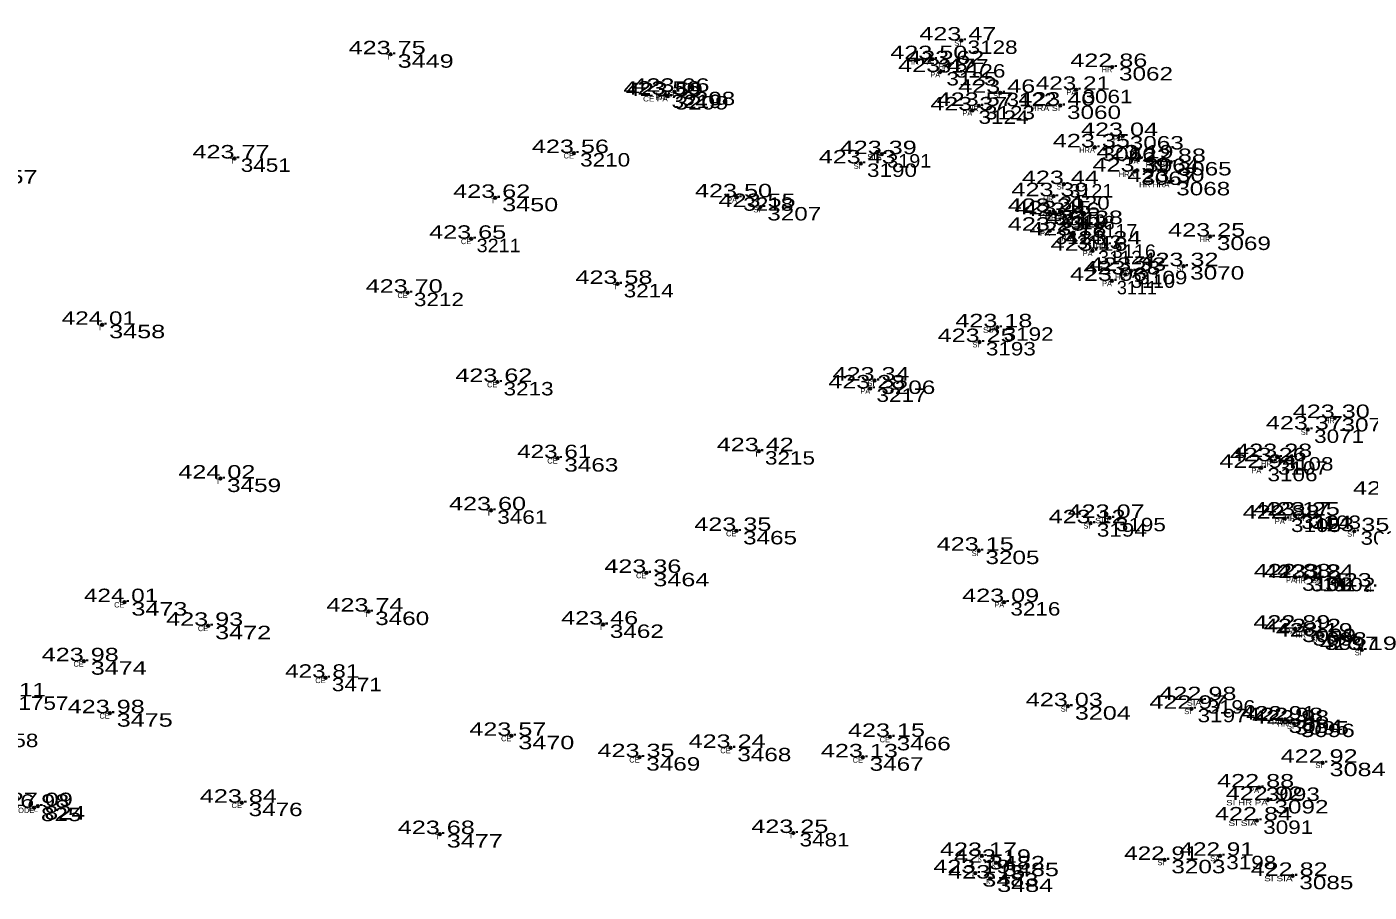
# Model space of a CAD drawing. Extents: x -639390 to -639074, y -1138747 to -1138358.
# Drawn here: x -639201.6 to -639126.7, y -1138617 to -1138568.7 of the extents above; entities that cross this region are included whole.
import ezdxf
from ezdxf.enums import TextEntityAlignment as Align

# ---------------------------------------------------------------- set-up
doc = ezdxf.new("R2010")
doc.units = 0
doc.header["$LTSCALE"] = 0.3
doc.header["$PDMODE"] = 32
doc.header["$PDSIZE"] = 0.15
for name, color, linetype in [('11', 7, 'Continuous'), ('12', 7, 'Continuous'), ('13', 7, 'Continuous'), ('57', 7, 'Continuous')]:
    doc.layers.add(name, color=color, linetype=linetype)

msp = doc.modelspace()

# ---------------------------------------------------------------- linework, layer by layer
at = {"layer": '11'}
for p in [(-639149.45, -1138569.5), (-639181.28, -1138570.27), (-639151.07, -1138570.54), (-639150.13, -1138570.82), (-639141.03, -1138570.98), (-639150.63, -1138571.26), (-639165.96, -1138572.52), (-639165.82, -1138572.6), (-639165.45, -1138572.36), (-639147.28, -1138572.42), (-639143.04, -1138572.25), (-639148.84, -1138573.4), (-639148.48, -1138573.15), (-639143.93, -1138573.13), (-639140.43, -1138574.83), (-639142, -1138575.46), (-639189.99, -1138576.08), (-639171.06, -1138575.78), (-639155.06, -1138576.36), (-639153.89, -1138575.84), (-639139.57, -1138576.08), (-639137.76, -1138576.28), (-639139.79, -1138576.81), (-639143.73, -1138577.51), (-639137.84, -1138577.39), (-639175.45, -1138578.28), (-639161.96, -1138578.25), (-639144.31, -1138578.19), (-639160.65, -1138578.79), (-639144.52, -1138579.06), (-639144.15, -1138579.2), (-639143.66, -1138579.29), (-639144.51, -1138580.11), (-639142.39, -1138579.74), (-639176.79, -1138580.56), (-639143.31, -1138580.37), (-639141.36, -1138580.88), (-639135.57, -1138580.44), (-639142.13, -1138581.23), (-639139.98, -1138582.35), (-639137.06, -1138582.09), (-639168.63, -1138583.08), (-639141.05, -1138582.91), (-639140.29, -1138582.55), (-639180.33, -1138583.57), (-639197.37, -1138585.36), (-639147.44, -1138585.5), (-639148.43, -1138586.32), (-639175.33, -1138588.55), (-639154.53, -1138588.91), (-639154.29, -1138588.47), (-639128.62, -1138590.56), (-639130.12, -1138591.2), (-639171.97, -1138592.8), (-639160.75, -1138592.41), (-639131.83, -1138592.74), (-639132.72, -1138593.34), (-639132.14, -1138592.97), (-639190.78, -1138593.94), (-639175.68, -1138595.71), (-639142.24, -1138596.43), (-639141.18, -1138596.13), (-639131.41, -1138596.17), (-639130.83, -1138596), (-639130.29, -1138596), (-639162, -1138596.86), (-639127.53, -1138596.88), (-639148.48, -1138597.96), (-639167.02, -1138599.2), (-639130.79, -1138599.45), (-639130.23, -1138599.48), (-639129.5, -1138599.47), (-639196.13, -1138600.83), (-639147.06, -1138600.83), (-639182.52, -1138601.36), (-639191.46, -1138602.15), (-639169.43, -1138602.08), (-639130.82, -1138602.31), (-639130.23, -1138602.51), (-639129.57, -1138602.75), (-639127.11, -1138603.5), (-639198.4, -1138604.13), (-639184.91, -1138605.05), (-639136.06, -1138606.3), (-639196.95, -1138607.03), (-639143.51, -1138606.64), (-639136.62, -1138606.78), (-639131.57, -1138607.38), (-639131.22, -1138607.47), (-639130.89, -1138607.61), (-639174.55, -1138608.29), (-639153.43, -1138608.35), (-639162.32, -1138608.96), (-639167.4, -1138609.48), (-639154.94, -1138609.49), (-639129.3, -1138609.79), (-639132.84, -1138611.17), (-639201.16, -1138612.3), (-639200.96, -1138612.21), (-639189.58, -1138612.02), (-639132.36, -1138611.87), (-639132.96, -1138613.01), (-639178.54, -1138613.77), (-639158.82, -1138613.71), (-639148.3, -1138614.99), (-639138.11, -1138615.21), (-639135.02, -1138614.98), (-639148.67, -1138615.95), (-639147.52, -1138615.37), (-639147.84, -1138616.25), (-639130.97, -1138616.1)]:
    msp.add_point(p, dxfattribs=at)

# ---------------------------------------------------------------- texts
at = {"layer": '12'}
for s, width, p in [('423.47 ', 1.4, (-639149.45, -1138569.5)), ('423.75 ', 1.4, (-639181.28, -1138570.27)), ('423.50 ', 1.4, (-639151.07, -1138570.54)), ('423.62 ', 1.4, (-639150.13, -1138570.82)), ('422.86 ', 1.4, (-639141.029, -1138570.98)), ('423.47 ', 1.4, (-639150.63, -1138571.26)), ('423.56 ', 1.4, (-639165.959, -1138572.52)), ('423.66 ', 1.4, (-639165.449, -1138572.36)), ('423.46 ', 1.4, (-639147.279, -1138572.42)), ('423.21 ', 1.35, (-639143.039, -1138572.25)), ('423.59 ', 1.4, (-639165.82, -1138572.6)), ('423.57 ', 1.4, (-639148.48, -1138573.15)), ('423.40 ', 1.4, (-639143.93, -1138573.13)), ('423.37 ', 1.4, (-639148.84, -1138573.4)), ('423.04 ', 1.4, (-639140.43, -1138574.83)), ('423.35 ', 1.4, (-639142, -1138575.46)), ('423.77 ', 1.4, (-639189.99, -1138576.08)), ('423.56 ', 1.4, (-639171.059, -1138575.78)), ('423.39 ', 1.4, (-639153.89, -1138575.84)), ('423.19 ', 1.4, (-639139.57, -1138576.08)), ('422.88 ', 1.4, (-639137.76, -1138576.28)), ('423.43 ', 1.4, (-639155.06, -1138576.36)), ('423.39 ', 1.4, (-639139.79, -1138576.81)), ('423.44 ', 1.4, (-639143.73, -1138577.51)), ('423.30 ', 1.4, (-639137.84, -1138577.39)), ('423.62 ', 1.4, (-639175.45, -1138578.28)), ('423.50 ', 1.4, (-639161.96, -1138578.25)), ('423.39 ', 1.4, (-639144.31, -1138578.19)), ('423.55 ', 1.4, (-639160.65, -1138578.79)), ('423.29 ', 1.4, (-639144.52, -1138579.06)), ('423.45 ', 1.4, (-639144.15, -1138579.2)), ('423.46 ', 1.4, (-639143.659, -1138579.29)), ('423.38 ', 1.4, (-639142.39, -1138579.74)), ('423.65 ', 1.4, (-639176.79, -1138580.56)), ('423.23 ', 1.4, (-639144.51, -1138580.11)), ('423.18 ', 1.4, (-639143.31, -1138580.37)), ('423.25 ', 1.4, (-639135.57, -1138580.44)), ('423.16 ', 1.4, (-639142.129, -1138581.23)), ('423.34 ', 1.4, (-639141.36, -1138580.88)), ('423.32 ', 1.4, (-639137.06, -1138582.09)), ('423.06 ', 1.4, (-639141.049, -1138582.91)), ('423.28 ', 1.4, (-639140.29, -1138582.55)), ('423.33 ', 1.4, (-639139.98, -1138582.35)), ('423.70 ', 1.4, (-639180.33, -1138583.57)), ('423.58 ', 1.4, (-639168.63, -1138583.08)), ('424.01 ', 1.35, (-639197.369, -1138585.36)), ('423.18 ', 1.4, (-639147.44, -1138585.5)), ('423.25 ', 1.4, (-639148.43, -1138586.32)), ('423.62 ', 1.4, (-639175.33, -1138588.55)), ('423.28 ', 1.4, (-639154.53, -1138588.91)), ('423.34 ', 1.4, (-639154.29, -1138588.47)), ('423.30 ', 1.4, (-639128.62, -1138590.56)), ('423.37 ', 1.4, (-639130.12, -1138591.2)), ('423.61 ', 1.35, (-639171.969, -1138592.8)), ('423.42 ', 1.4, (-639160.75, -1138592.41)), ('423.28 ', 1.4, (-639131.83, -1138592.74)), ('422.94 ', 1.4, (-639132.72, -1138593.34)), ('423.26 ', 1.4, (-639132.139, -1138592.97)), ('424.02 ', 1.4, (-639190.78, -1138593.94)), ('423.27 ', 1.4, (-639125.26, -1138594.84)), ('423.60 ', 1.4, (-639175.68, -1138595.71)), ('423.12 ', 1.4, (-639142.24, -1138596.43)), ('423.07 ', 1.4, (-639141.18, -1138596.13)), ('422.88 ', 1.4, (-639131.41, -1138596.17)), ('423.17 ', 1.4, (-639130.83, -1138596)), ('423.25 ', 1.4, (-639130.29, -1138596)), ('423.35 ', 1.4, (-639162, -1138596.86)), ('423.35 ', 1.4, (-639127.53, -1138596.88)), ('423.15 ', 1.4, (-639148.48, -1138597.96)), ('423.36 ', 1.4, (-639167.019, -1138599.2)), ('422.88 ', 1.4, (-639130.79, -1138599.45)), ('423.18 ', 1.4, (-639130.23, -1138599.48)), ('423.24 ', 1.4, (-639129.5, -1138599.47)), ('423.28 ', 1.4, (-639126.56, -1138599.96)), ('424.01 ', 1.35, (-639196.129, -1138600.83)), ('423.09 ', 1.4, (-639147.06, -1138600.83)), ('423.74 ', 1.4, (-639182.52, -1138601.36)), ('423.93 ', 1.4, (-639191.46, -1138602.15)), ('423.46 ', 1.4, (-639169.429, -1138602.08)), ('422.89 ', 1.4, (-639130.82, -1138602.31)), ('423.12 ', 1.4, (-639130.23, -1138602.51)), ('423.19 ', 1.4, (-639129.57, -1138602.75)), ('423.19 ', 1.4, (-639127.11, -1138603.5)), ('423.98 ', 1.4, (-639198.4, -1138604.13)), ('423.81 ', 1.35, (-639184.909, -1138605.05)), ('424.11 ', 1.35, (-639202.389, -1138606.09)), ('423.98 ', 1.4, (-639196.95, -1138607.03)), ('423.03 ', 1.4, (-639143.51, -1138606.64)), ('422.97 ', 1.4, (-639136.62, -1138606.78)), ('422.98 ', 1.4, (-639136.06, -1138606.3)), ('422.91 ', 1.35, (-639131.569, -1138607.38)), ('422.98 ', 1.4, (-639131.22, -1138607.47)), ('422.98 ', 1.4, (-639130.89, -1138607.61)), ('423.57 ', 1.4, (-639174.55, -1138608.29)), ('423.15 ', 1.4, (-639153.43, -1138608.35)), ('423.24 ', 1.4, (-639162.32, -1138608.96)), ('423.35 ', 1.4, (-639167.4, -1138609.48)), ('423.13 ', 1.4, (-639154.94, -1138609.49)), ('422.92 ', 1.4, (-639129.3, -1138609.79)), ('422.88 ', 1.4, (-639132.84, -1138611.17)), ('427.09 ', 1.4, (-639200.96, -1138612.21)), ('423.84 ', 1.4, (-639189.58, -1138612.02)), ('422.92 ', 1.4, (-639132.36, -1138611.87)), ('426.98 ', 1.4, (-639201.16, -1138612.3)), ('422.84 ', 1.4, (-639132.96, -1138613.01)), ('423.68 ', 1.4, (-639178.54, -1138613.77)), ('423.25 ', 1.4, (-639158.82, -1138613.71)), ('423.17 ', 1.4, (-639148.3, -1138614.99)), ('422.91 ', 1.35, (-639138.109, -1138615.21)), ('422.91 ', 1.35, (-639135.019, -1138614.98)), ('423.19 ', 1.4, (-639148.67, -1138615.95)), ('423.19 ', 1.4, (-639147.52, -1138615.37)), ('423.15 ', 1.4, (-639147.84, -1138616.25)), ('422.82 ', 1.4, (-639130.97, -1138616.1))]:
    msp.add_text(s, height=0.75, dxfattribs=dict(at, width=width)).set_placement(p, align=Align.CENTER)
at = {"layer": '13'}
for s, width, p in [(' 3128', 1.25, (-639149.45, -1138570.25)), (' 3449', 1.4, (-639181.28, -1138571.02)), (' 3127', 1.25, (-639151.07, -1138571.29)), (' 3126', 1.25, (-639150.13, -1138571.57)), (' 3062', 1.35, (-639141.03, -1138571.73)), (' 3125', 1.25, (-639150.63, -1138572.01)), (' 3219', 1.25, (-639165.96, -1138573.27)), (' 3208', 1.35, (-639165.45, -1138573.11)), (' 3122', 1.25, (-639147.28, -1138573.17)), (' 3061', 1.25, (-639143.04, -1138573)), (' 3209', 1.35, (-639165.82, -1138573.35)), (' 3123', 1.25, (-639148.48, -1138573.9)), (' 3060', 1.35, (-639143.93, -1138573.88)), (' 3124', 1.25, (-639148.84, -1138574.15)), (' 3063', 1.35, (-639140.43, -1138575.58)), (' 3066', 1.35, (-639142, -1138576.21)), (' 3451', 1.25, (-639189.99, -1138576.83)), (' 3210', 1.25, (-639171.06, -1138576.53)), (' 3191', 1.1, (-639153.89, -1138576.59)), (' 3064', 1.35, (-639139.57, -1138576.83)), (' 3065', 1.35, (-639137.76, -1138577.03)), (' 3457', 1.4, (-639204.49, -1138577.48)), (' 3190', 1.25, (-639155.06, -1138577.11)), (' 3067', 1.35, (-639139.79, -1138577.56)), (' 3121', 1.1, (-639143.73, -1138578.26)), (' 3068', 1.35, (-639137.84, -1138578.14)), (' 3450', 1.4, (-639175.45, -1138579.03)), (' 3218', 1.25, (-639161.96, -1138579)), (' 3120', 1.25, (-639144.31, -1138578.94)), (' 3207', 1.35, (-639160.65, -1138579.54)), (' 3115', 1.1, (-639144.52, -1138579.81)), (' 3119', 1.1, (-639144.15, -1138579.95)), (' 3118', 1.1, (-639143.66, -1138580.04)), (' 3117', 1.1, (-639142.39, -1138580.49)), (' 3211', 1.1, (-639176.79, -1138581.31)), (' 3114', 1.15, (-639144.51, -1138580.86)), (' 3113', 1.1, (-639143.31, -1138581.12)), (' 3069', 1.35, (-639135.57, -1138581.19)), (' 3112', 1.1, (-639142.13, -1138581.98)), (' 3116', 1.1, (-639141.36, -1138581.63)), (' 3070', 1.35, (-639137.06, -1138582.84)), (' 3110', 1.1, (-639140.29, -1138583.3)), (' 3109', 1.25, (-639139.98, -1138583.1)), (' 3212', 1.25, (-639180.33, -1138584.32)), (' 3214', 1.25, (-639168.63, -1138583.83)), (' 3458', 1.4, (-639197.37, -1138586.11)), (' 3192', 1.25, (-639147.44, -1138586.25)), (' 3193', 1.25, (-639148.43, -1138587.07)), (' 3213', 1.25, (-639175.33, -1138589.3)), (' 3217', 1.25, (-639154.53, -1138589.66)), (' 3206', 1.35, (-639154.29, -1138589.22)), (' 3072', 1.35, (-639128.62, -1138591.31)), (' 3071', 1.25, (-639130.12, -1138591.95)), (' 3463', 1.35, (-639171.97, -1138593.55)), (' 3215', 1.25, (-639160.75, -1138593.16)), (' 3108', 1.25, (-639131.83, -1138593.49)), (' 3106', 1.25, (-639132.72, -1138594.09)), (' 3107', 1.25, (-639132.14, -1138593.72)), (' 3459', 1.35, (-639190.78, -1138594.69)), (' 3461', 1.25, (-639175.68, -1138596.46)), (' 3194', 1.25, (-639142.24, -1138597.18)), (' 3195', 1.25, (-639141.18, -1138596.88)), (' 3105', 1.25, (-639131.41, -1138596.92)), (' 3104', 1.25, (-639130.83, -1138596.75)), (' 3103', 1.25, (-639130.29, -1138596.75)), (' 3465', 1.35, (-639162, -1138597.61)), (' 3081', 1.25, (-639127.53, -1138597.63)), (' 3205', 1.35, (-639148.48, -1138598.71)), (' 3464', 1.4, (-639167.02, -1138599.95)), (' 3100', 1.25, (-639130.79, -1138600.2)), (' 3101', 1.1, (-639130.23, -1138600.23)), (' 3102', 1.25, (-639129.5, -1138600.22)), (' 3473', 1.4, (-639196.13, -1138601.58)), (' 3216', 1.25, (-639147.06, -1138601.58)), (' 3460', 1.35, (-639182.52, -1138602.11)), (' 3472', 1.4, (-639191.46, -1138602.9)), (' 3462', 1.35, (-639169.43, -1138602.83)), (' 3099', 1.35, (-639130.82, -1138603.06)), (' 3098', 1.35, (-639130.23, -1138603.26)), (' 3097', 1.35, (-639129.57, -1138603.5)), (' 3474', 1.4, (-639198.4, -1138604.88)), (' 3471', 1.25, (-639184.91, -1138605.8)), (' 1757', 1.25, (-639202.39, -1138606.84)), (' 3475', 1.4, (-639196.95, -1138607.78)), (' 3204', 1.4, (-639143.51, -1138607.39)), (' 3197', 1.25, (-639136.62, -1138607.53)), (' 3196', 1.2, (-639136.06, -1138607.05)), (' 3094', 1.35, (-639131.57, -1138608.13)), (' 3095', 1.35, (-639131.22, -1138608.22)), (' 3096', 1.35, (-639130.89, -1138608.36)), (' 1758', 1.25, (-639204.07, -1138608.92)), (' 3470', 1.4, (-639174.55, -1138609.04)), (' 3466', 1.35, (-639153.43, -1138609.1)), (' 3468', 1.35, (-639162.32, -1138609.71)), (' 3469', 1.35, (-639167.4, -1138610.23)), (' 3467', 1.35, (-639154.94, -1138610.24)), (' 3084', 1.4, (-639129.3, -1138610.54)), (' 3093', 1.35, (-639132.84, -1138611.92)), (' 824', 1.35, (-639200.96, -1138612.96)), (' 3476', 1.35, (-639189.58, -1138612.77)), (' 3092', 1.35, (-639132.36, -1138612.62)), (' 825', 1.35, (-639201.16, -1138613.05)), (' 3091', 1.25, (-639132.96, -1138613.76)), (' 3477', 1.4, (-639178.54, -1138614.52)), (' 3481', 1.25, (-639158.82, -1138614.46)), (' 3482', 1.4, (-639148.3, -1138615.74)), (' 3203', 1.35, (-639138.11, -1138615.96)), (' 3198', 1.25, (-639135.02, -1138615.73)), (' 3483', 1.4, (-639148.67, -1138616.7)), (' 3485', 1.4, (-639147.52, -1138616.12)), (' 3484', 1.4, (-639147.84, -1138617)), (' 3085', 1.35, (-639130.97, -1138616.85))]:
    msp.add_text(s, height=0.75, dxfattribs=dict(at, width=width)).set_placement(p)
msp.add_text(' 3111', height=0.75, dxfattribs=at).set_placement((-639141.05, -1138583.66))
at = {"layer": '57'}
for s, width, p in [('SI', 1.05, (-639149.45, -1138569.8)), ('T', 0.85, (-639181.28, -1138570.57)), ('HR PA', 1.15, (-639151.07, -1138570.84)), ('HR', 0.85, (-639150.129, -1138571.12)), ('HR', 0.85, (-639141.029, -1138571.28)), ('PA', 0.95, (-639150.63, -1138571.56)), ('PA', 0.95, (-639165.96, -1138572.82)), ('SI', 1.05, (-639165.45, -1138572.66)), ('SI', 1.05, (-639147.28, -1138572.72)), ('PA', 0.95, (-639143.04, -1138572.55)), ('CE PA', 1.15, (-639165.82, -1138572.9)), ('HR', 0.85, (-639148.479, -1138573.45)), ('HRA SI', 1.25, (-639143.93, -1138573.43)), ('PA', 0.95, (-639148.84, -1138573.7)), ('PA', 0.95, (-639140.43, -1138575.13)), ('HRA', 0.95, (-639142, -1138575.76)), ('T', 0.85, (-639189.99, -1138576.38)), ('CE', 0.9, (-639171.06, -1138576.08)), ('SIA', 1.25, (-639153.89, -1138576.14)), ('PA', 0.95, (-639139.57, -1138576.38)), ('PA HR', 1.15, (-639137.759, -1138576.58)), ('SI', 1.05, (-639155.06, -1138576.66)), ('HRA', 0.95, (-639139.79, -1138577.11)), ('SI', 1.05, (-639143.73, -1138577.81)), ('HR HRA', 1.1, (-639137.84, -1138577.69)), ('T', 0.85, (-639175.45, -1138578.58)), ('PA', 0.95, (-639161.96, -1138578.55)), ('HR', 0.85, (-639144.309, -1138578.49)), ('SI', 1.05, (-639160.65, -1138579.09)), ('PA', 0.95, (-639144.52, -1138579.36)), ('HR', 0.85, (-639144.149, -1138579.5)), ('HR', 0.85, (-639143.659, -1138579.59)), ('HR', 0.85, (-639142.389, -1138580.04)), ('CE', 0.9, (-639176.79, -1138580.86)), ('PA', 0.95, (-639144.51, -1138580.41)), ('PA', 0.95, (-639143.31, -1138580.67)), ('HR', 0.85, (-639135.569, -1138580.74)), ('PA', 0.95, (-639142.13, -1138581.53)), ('HR', 0.85, (-639141.359, -1138581.18)), ('SI', 1.05, (-639137.06, -1138582.39)), ('PA', 0.95, (-639141.05, -1138583.21)), ('HR', 0.85, (-639140.289, -1138582.85)), ('SI', 1.05, (-639139.98, -1138582.65)), ('CE', 0.9, (-639180.33, -1138583.87)), ('T', 0.85, (-639168.63, -1138583.38)), ('T', 0.85, (-639197.37, -1138585.66)), ('SIA', 1.25, (-639147.44, -1138585.8)), ('SI', 1.05, (-639148.43, -1138586.62)), ('CE', 0.9, (-639175.33, -1138588.85)), ('PA', 0.95, (-639154.53, -1138589.21)), ('SI', 1.05, (-639154.29, -1138588.77)), ('SI', 1.05, (-639130.12, -1138591.5)), ('HR', 0.85, (-639128.619, -1138590.86)), ('CE', 0.9, (-639171.97, -1138593.1)), ('T', 0.85, (-639160.75, -1138592.71)), ('SI', 1.05, (-639131.83, -1138593.04)), ('PA', 0.95, (-639132.72, -1138593.64)), ('HR', 0.85, (-639132.139, -1138593.27)), ('T', 0.85, (-639190.78, -1138594.24)), ('T', 0.85, (-639175.68, -1138596.01)), ('SI', 1.05, (-639142.24, -1138596.73)), ('SIA', 1.25, (-639141.18, -1138596.43)), ('PA', 0.95, (-639131.41, -1138596.47)), ('HR', 0.85, (-639130.829, -1138596.3)), ('SI', 1.05, (-639130.29, -1138596.3)), ('CE', 0.9, (-639162, -1138597.16)), ('SI', 1.05, (-639127.53, -1138597.18)), ('SI', 1.05, (-639148.48, -1138598.26)), ('CE', 0.9, (-639167.02, -1138599.5)), ('PA', 0.95, (-639130.79, -1138599.75)), ('HR', 0.85, (-639130.229, -1138599.78)), ('SI', 1.05, (-639129.5, -1138599.77)), ('SI', 1.05, (-639126.56, -1138600.26)), ('CE', 0.9, (-639196.13, -1138601.13)), ('PA', 0.95, (-639147.06, -1138601.13)), ('T', 0.85, (-639182.52, -1138601.66)), ('CE', 0.9, (-639191.46, -1138602.45)), ('T', 0.85, (-639169.43, -1138602.38)), ('PA', 0.95, (-639130.82, -1138602.61)), ('HR', 0.85, (-639130.229, -1138602.81)), ('SI', 1.05, (-639129.57, -1138603.05)), ('SI', 1.05, (-639127.11, -1138603.8)), ('CE', 0.9, (-639198.4, -1138604.43)), ('CE', 0.9, (-639184.91, -1138605.35)), ('SI', 1.05, (-639143.51, -1138606.94)), ('SI', 1.05, (-639136.62, -1138607.08)), ('SIA', 1.25, (-639136.06, -1138606.6)), ('CE', 0.9, (-639196.95, -1138607.33)), ('PA', 0.95, (-639131.57, -1138607.68)), ('HR', 0.85, (-639131.219, -1138607.77)), ('SI', 1.05, (-639130.89, -1138607.91)), ('CE', 0.9, (-639174.55, -1138608.59)), ('CE', 0.9, (-639153.43, -1138608.65)), ('CE', 0.9, (-639162.32, -1138609.26)), ('CE', 0.9, (-639167.4, -1138609.78)), ('CE', 0.9, (-639154.94, -1138609.79)), ('SI', 1.05, (-639129.3, -1138610.09)), ('PA', 0.95, (-639132.84, -1138611.47)), ('CE', 0.9, (-639189.58, -1138612.32)), ('SI HR PA', 1.35, (-639132.36, -1138612.17)), ('PODE', 0.95, (-639201.16, -1138612.6)), ('SI SIA', 1.4, (-639132.96, -1138613.31)), ('T', 0.85, (-639158.82, -1138614.01)), ('T', 0.85, (-639178.54, -1138614.07)), ('K', 0.65, (-639148.299, -1138615.29)), ('SI', 1.05, (-639138.11, -1138615.51)), ('SA', 0.95, (-639135.02, -1138615.28)), ('K', 0.65, (-639148.669, -1138616.25)), ('K', 0.65, (-639147.519, -1138615.67)), ('K', 0.65, (-639147.839, -1138616.55)), ('SI SIA', 1.4, (-639130.97, -1138616.4))]:
    msp.add_text(s, height=0.3, dxfattribs=dict(at, width=width)).set_placement(p, align=Align.RIGHT)
msp.add_text('PL', height=0.3, dxfattribs=at).set_placement((-639200.959, -1138612.51), align=Align.RIGHT)

doc.saveas('drawing.dxf')
